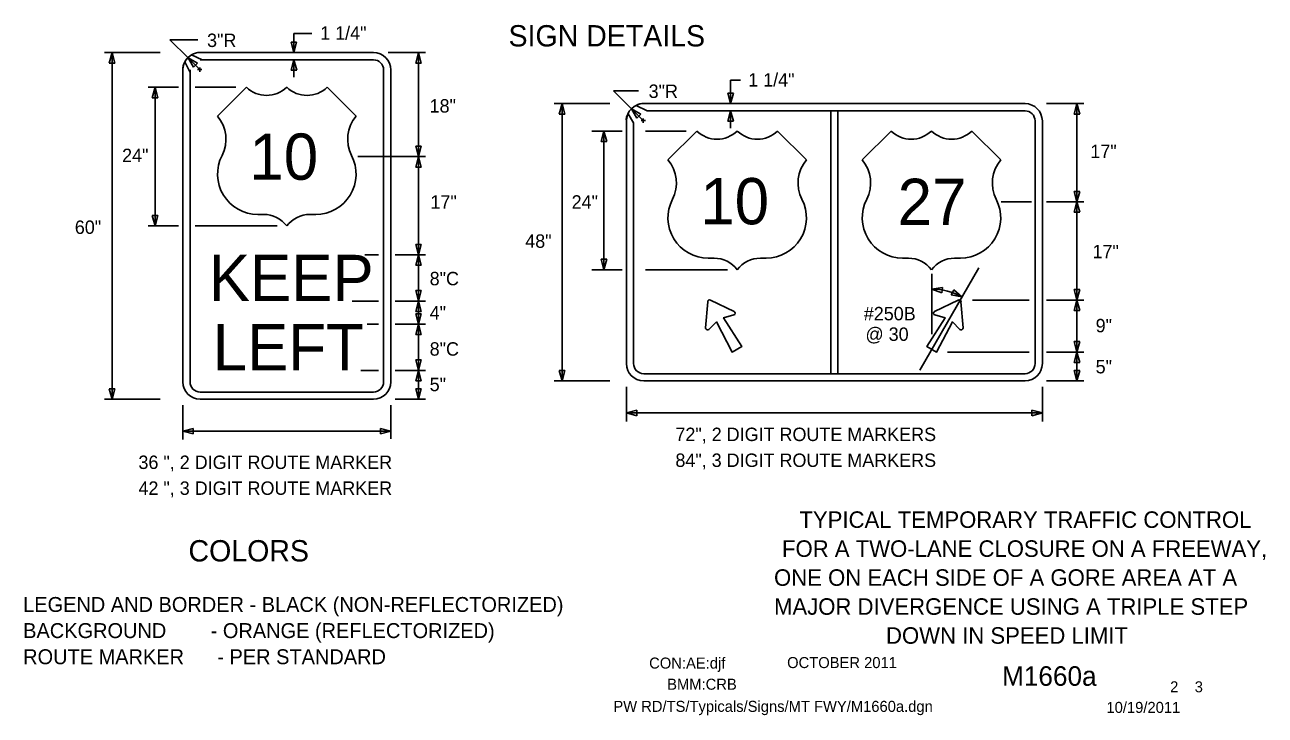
# Model space of a CAD drawing. Extents: x 16519 to 19508, y 5743 to 6974.
# Drawn here: x 17768 to 18466, y 5932 to 6320 of the extents above; entities that cross this region are included whole.
import ezdxf

# ---------------------------------------------------------------- set-up
doc = ezdxf.new("R2010")
doc.units = 0
for name, color, linetype in [('BORDER', 7, 'Continuous'), ('BORDER_SIGNAL_WO', 7, 'Continuous'), ('TRAFFIC_SIGNS_PR', 7, 'Continuous'), ('TYPICAL_EX', 7, 'Continuous'), ('TYPICAL_TEXT_DIMEN_PR', 7, 'Continuous')]:
    doc.layers.add(name, color=color, linetype=linetype)

msp = doc.modelspace()

# ---------------------------------------------------------------- linework, layer by layer
at = {"layer": 'TRAFFIC_SIGNS_PR'}
for p, q in [((17859.5, 6300.96), (17858.5, 6299.45)), ((17868.29, 6300.52), (17862.19, 6303.27)), ((17867.09, 6304.58), (17964.59, 6304.58)), ((17857.34, 6119.33), (17857.34, 6294.83)), ((17858.53, 6299.39), (17861.4, 6293.35)), ((17861.4, 6294.83), (17861.4, 6119.33)), ((17964.59, 6300.52), (17867.09, 6300.52)), ((17970.27, 6119.33), (17970.27, 6294.83)), ((17974.34, 6294.83), (17974.34, 6119.33)), ((18118.56, 6271.83), (18112.33, 6274.85)), ((18116.61, 6275.88), (18331.11, 6275.88)), ((18116.61, 6275.88), (18331.11, 6275.88)), ((18106.86, 6266.13), (18106.86, 6129.63)), ((18106.86, 6129.63), (18106.86, 6266.13)), ((18107.78, 6270.14), (18110.91, 6265.1)), ((18118.55, 6271.82), (18221.83, 6271.82)), ((18331.11, 6271.82), (18118.55, 6271.82)), ((18221.83, 6271.82), (18221.83, 6123.95)), ((18225.89, 6271.82), (18225.89, 6123.95)), ((18225.89, 6271.82), (18331.11, 6271.82)), ((18336.8, 6266.13), (18336.8, 6220.38)), ((18336.8, 6129.63), (18336.8, 6266.13)), ((18340.86, 6266.13), (18340.86, 6129.63)), ((18340.86, 6266.13), (18340.86, 6129.63)), ((18110.92, 6265.08), (18110.92, 6129.63)), ((18110.92, 6265.08), (18110.92, 6129.63)), ((18336.8, 6220.38), (18336.8, 6129.63)), ((18151.46, 6149.74), (18152.61, 6164.46)), ((18154.12, 6165.33), (18167.44, 6158.97)), ((18293.59, 6165.33), (18280.28, 6158.97)), ((18296.26, 6149.74), (18295.1, 6164.46)), ((18116.61, 6123.95), (18331.11, 6123.95)), ((18116.61, 6119.88), (18331.11, 6119.88)), ((18331.11, 6119.88), (18116.61, 6119.88)), ((17867.09, 6113.64), (17964.59, 6113.64)), ((17964.59, 6109.58), (17867.09, 6109.58))]:
    msp.add_line(p, q, dxfattribs=at)
for points in [[(18118.55, 6271.82), (18118.53, 6271.83)], [(18110.91, 6265.1), (18110.92, 6265.08)], [(18167.28, 6157), (18161.55, 6155.42), (18171.77, 6139.25), (18166.37, 6136.13), (18157.48, 6153.07), (18153.25, 6148.9)], [(18280.44, 6157), (18286.16, 6155.42), (18275.95, 6139.25), (18281.34, 6136.13), (18290.24, 6153.07), (18294.46, 6148.9)]]:
    msp.add_lwpolyline(points, dxfattribs=at)
msp.add_lwpolyline([(18221.83, 6271.82), (18225.89, 6271.82), (18225.89, 6123.95), (18221.83, 6123.95)], close=True, dxfattribs=at)
for centre, radius, start, end in [((17867.09, 6294.83), 9.75, 90, 180), ((17866.5, 6297.01), 7.6, 85.58319, 124.53531), ((17964.59, 6294.83), 9.75, 0, 90), ((17864.37, 6295.43), 7.06, 145.86811, 184.82317), ((17855.94, 6294.09), 5.51, 352.24294, 7.75653), ((17867.69, 6304.95), 4.47, 262.2432, 277.7568), ((17964.59, 6294.83), 5.69, 0, 90), ((18116.61, 6266.13), 9.75, 90, 180), ((18116.61, 6266.13), 9.75, 90, 180), ((18115.93, 6269.32), 6.6, 84.11162, 123.06374), ((18331.11, 6266.13), 9.75, 0, 90), ((18331.11, 6266.13), 9.75, 0, 90), ((18112.99, 6266.84), 6.17, 147.60925, 186.56283), ((18117.55, 6279), 7.24, 277.81035, 278.05403), ((18331.11, 6266.13), 5.69, 0, 89.99421), ((18331.11, 6266.13), 5.69, 0, 90), ((18153.67, 6164.37), 1.06, 64.48226, 175.51774), ((18294.05, 6164.37), 1.06, 4.48226, 115.51774), ((18166.98, 6158.02), 1.06, 285.9885, 64.48226), ((18280.73, 6158.02), 1.06, 115.51774, 254.0115), ((18152.52, 6149.66), 1.06, 175.51775, 314.01151), ((18295.2, 6149.66), 1.06, 225.98849, 4.48225), ((18116.61, 6129.63), 9.75, 180, 270), ((18116.61, 6129.63), 9.75, 180, 270), ((18116.61, 6129.63), 5.69, 180, 270), ((18116.61, 6129.63), 5.69, 180, 270), ((18331.11, 6129.63), 9.75, 270, 0), ((18331.11, 6129.63), 5.69, 270, 0), ((18331.11, 6129.63), 9.75, 270, 0), ((18331.11, 6129.63), 5.69, 270, 0), ((17867.09, 6119.33), 9.75, 180, 270), ((17867.09, 6119.33), 5.69, 180, 270), ((17964.59, 6119.33), 5.69, 270, 0), ((17964.59, 6119.33), 9.75, 270, 0)]:
    msp.add_arc(centre, radius, start, end, dxfattribs=at)
at = {"layer": 'TYPICAL_EX'}
for p, q in [((17876.84, 6268.84), (17893.09, 6285.09)), ((17954.84, 6268.84), (17938.59, 6285.09)), ((18130.22, 6244.22), (18146.47, 6260.47)), ((18208.22, 6244.22), (18191.97, 6260.47)), ((18239.5, 6244.22), (18255.75, 6260.47)), ((18317.5, 6244.22), (18301.25, 6260.47)), ((17899.56, 6213.54), (17902.81, 6213.54)), ((17932.11, 6213.54), (17928.86, 6213.54)), ((18152.95, 6188.93), (18156.2, 6188.93)), ((18185.49, 6188.93), (18182.24, 6188.93)), ((18262.22, 6188.93), (18265.47, 6188.93)), ((18294.77, 6188.93), (18291.52, 6188.93))]:
    msp.add_line(p, q, dxfattribs=at)
for centre, radius, start, end in [((17904.46, 6296.92), 16.42, 226.14041, 313.85958), ((17927.21, 6296.92), 16.42, 226.14042, 313.85959), ((17861.44, 6255.82), 20.16, 333.09768, 40.19361), ((17970.24, 6255.82), 20.16, 139.80639, 206.90233), ((18157.85, 6272.31), 16.42, 226.14041, 313.85958), ((18180.59, 6272.31), 16.42, 226.14042, 313.85959), ((18267.12, 6272.31), 16.42, 226.14041, 313.85958), ((18289.87, 6272.31), 16.42, 226.14042, 313.85959), ((17899.6, 6236.27), 22.73, 152.6698, 269.90132), ((17932.07, 6236.27), 22.73, 270.09868, 27.3302), ((18114.82, 6231.21), 20.16, 333.09768, 40.19361), ((18223.62, 6231.21), 20.16, 139.80639, 206.90233), ((18224.1, 6231.21), 20.16, 333.09768, 40.19361), ((18332.9, 6231.21), 20.16, 139.80639, 206.90233), ((18152.99, 6211.66), 22.73, 152.6698, 269.90132), ((18185.45, 6211.66), 22.73, 270.09868, 27.3302), ((18262.27, 6211.66), 22.73, 152.6698, 269.90132), ((18294.73, 6211.66), 22.73, 270.09868, 27.3302), ((17902.85, 6197.26), 16.28, 37.1038, 90.13853), ((17928.82, 6197.26), 16.28, 89.86147, 142.8962), ((18156.24, 6172.65), 16.28, 37.1038, 90.13853), ((18182.2, 6172.65), 16.28, 89.86147, 142.8962), ((18265.52, 6172.65), 16.28, 37.1038, 90.13853), ((18291.48, 6172.65), 16.28, 89.86147, 142.8962)]:
    msp.add_arc(centre, radius, start, end, dxfattribs=at)
at = {"layer": 'TYPICAL_TEXT_DIMEN_PR'}
for p, q in [((17919.81, 6315.34), (17919.81, 6304.58)), ((17919.81, 6315.34), (17929.91, 6315.34)), ((17865.71, 6311.86), (17850.05, 6311.86)), ((17850.05, 6311.86), (17860.29, 6301.63)), ((17919.81, 6304.58), (17918.24, 6310.44)), ((17918.24, 6310.44), (17919.81, 6310.44)), ((17919.81, 6310.44), (17921.38, 6310.44)), ((17921.38, 6310.44), (17919.81, 6304.58)), ((17844.51, 6304.58), (17813.21, 6304.58)), ((17815.98, 6298.72), (17817.55, 6304.58)), ((17817.55, 6304.58), (17817.55, 6109.58)), ((17817.55, 6304.58), (17819.12, 6298.72)), ((17860.29, 6301.63), (17866.85, 6295.07)), ((17863.32, 6296.37), (17860.29, 6301.63)), ((17860.29, 6301.63), (17865.54, 6298.6)), ((17972.88, 6304.58), (17993.84, 6304.58)), ((17988.37, 6298.72), (17989.94, 6304.58)), ((17989.94, 6304.58), (17989.94, 6246.08)), ((17989.94, 6304.58), (17991.51, 6298.72)), ((17817.55, 6298.72), (17815.98, 6298.72)), ((17819.12, 6298.72), (17817.55, 6298.72)), ((17864.43, 6297.49), (17863.32, 6296.37)), ((17865.54, 6298.6), (17864.43, 6297.49)), ((17865.64, 6295.07), (17868.05, 6295.07)), ((17866.85, 6293.86), (17866.85, 6296.28)), ((17918.28, 6294.66), (17919.86, 6300.52)), ((17919.86, 6294.66), (17918.28, 6294.66)), ((17919.86, 6300.52), (17919.86, 6290.77)), ((17919.86, 6300.52), (17921.43, 6294.66)), ((17921.43, 6294.66), (17919.86, 6294.66)), ((17989.94, 6298.72), (17988.37, 6298.72)), ((17991.51, 6298.72), (17989.94, 6298.72)), ((18165.47, 6289.03), (18165.47, 6275.88)), ((18165.47, 6289.03), (18170.99, 6289.03)), ((17854.96, 6285.08), (17837.84, 6285.08)), ((17840.16, 6279.22), (17841.73, 6285.08)), ((17841.73, 6285.08), (17841.73, 6207.08)), ((17841.73, 6285.08), (17843.3, 6279.22)), ((17887.2, 6285.08), (17864.33, 6285.08)), ((18113.75, 6283.17), (18099.57, 6283.17)), ((18099.57, 6283.17), (18109.72, 6273.02)), ((18165.47, 6275.88), (18163.89, 6281.74)), ((18163.89, 6281.74), (18165.47, 6281.74)), ((18165.47, 6281.74), (18167.04, 6281.74)), ((18167.04, 6281.74), (18165.47, 6275.88)), ((17841.73, 6279.22), (17840.16, 6279.22)), ((17843.3, 6279.22), (17841.73, 6279.22)), ((18097.62, 6275.88), (18066.33, 6275.88)), ((18069.1, 6270.02), (18070.67, 6275.88)), ((18070.67, 6275.88), (18070.67, 6119.88)), ((18070.67, 6275.88), (18072.24, 6270.02)), ((18109.72, 6273.02), (18116.37, 6266.37)), ((18112.76, 6267.76), (18109.72, 6273.02)), ((18109.72, 6273.02), (18114.98, 6269.99)), ((18343.23, 6275.88), (18364.19, 6275.88)), ((18358.72, 6270.02), (18360.29, 6275.88)), ((18360.29, 6275.88), (18360.29, 6220.63)), ((18360.29, 6275.88), (18361.86, 6270.02)), ((18070.67, 6270.02), (18069.1, 6270.02)), ((18072.24, 6270.02), (18070.67, 6270.02)), ((18113.87, 6268.88), (18112.76, 6267.76)), ((18114.98, 6269.99), (18113.87, 6268.88)), ((18115.16, 6266.37), (18117.58, 6266.37)), ((18116.37, 6265.16), (18116.37, 6267.58)), ((18163.94, 6265.96), (18165.51, 6271.82)), ((18163.94, 6265.96), (18165.51, 6271.82)), ((18165.51, 6271.82), (18165.51, 6262.07)), ((18165.51, 6271.82), (18167.08, 6265.96)), ((18165.51, 6271.82), (18167.08, 6265.96)), ((18360.29, 6270.02), (18358.72, 6270.02)), ((18361.86, 6270.02), (18360.29, 6270.02)), ((18104.49, 6260.47), (18087.36, 6260.47)), ((18092.65, 6254.61), (18094.23, 6260.47)), ((18094.23, 6260.47), (18094.23, 6182.47)), ((18094.23, 6260.47), (18095.8, 6254.61)), ((18140.59, 6260.47), (18117.71, 6260.47)), ((18165.51, 6265.96), (18163.94, 6265.96)), ((18165.51, 6265.96), (18163.94, 6265.96)), ((18167.08, 6265.96), (18165.51, 6265.96)), ((18167.08, 6265.96), (18165.51, 6265.96)), ((18094.23, 6254.61), (18092.65, 6254.61)), ((18095.8, 6254.61), (18094.23, 6254.61)), ((17955.73, 6246.08), (17993.84, 6246.08)), ((17989.94, 6246.08), (17988.37, 6251.94)), ((17988.37, 6251.94), (17989.94, 6251.94)), ((17988.37, 6240.22), (17989.94, 6246.08)), ((17989.94, 6251.94), (17991.51, 6251.94)), ((17991.51, 6251.94), (17989.94, 6246.08)), ((17989.94, 6246.08), (17989.94, 6190.83)), ((17989.94, 6246.08), (17991.51, 6240.22)), ((17989.94, 6240.22), (17988.37, 6240.22)), ((17991.51, 6240.22), (17989.94, 6240.22)), ((18360.29, 6220.63), (18358.72, 6226.49)), ((18358.72, 6226.49), (18360.29, 6226.49)), ((18360.29, 6226.49), (18361.86, 6226.49)), ((18361.86, 6226.49), (18360.29, 6220.63)), ((18317.67, 6220.63), (18334.82, 6220.63)), ((18343.23, 6220.63), (18364.19, 6220.63)), ((18358.72, 6214.77), (18360.29, 6220.63)), ((18360.29, 6220.63), (18360.29, 6165.38)), ((18360.29, 6220.63), (18361.86, 6214.77)), ((17841.73, 6207.08), (17840.16, 6212.94)), ((17840.16, 6212.94), (17841.73, 6212.94)), ((17841.73, 6212.94), (17843.3, 6212.94)), ((17843.3, 6212.94), (17841.73, 6207.08)), ((18360.29, 6214.77), (18358.72, 6214.77)), ((18361.86, 6214.77), (18360.29, 6214.77)), ((17854.96, 6207.08), (17837.84, 6207.08)), ((17910.33, 6207.08), (17864.33, 6207.08)), ((17989.94, 6190.83), (17988.37, 6196.69)), ((17988.37, 6196.69), (17989.94, 6196.69)), ((17989.94, 6196.69), (17991.51, 6196.69)), ((17991.51, 6196.69), (17989.94, 6190.83)), ((17959.66, 6190.83), (17967.35, 6190.83)), ((17976.71, 6190.83), (17993.84, 6190.83)), ((17988.37, 6184.97), (17989.94, 6190.83)), ((17989.94, 6190.83), (17989.94, 6164.83)), ((17989.94, 6190.83), (17991.51, 6184.97)), ((17989.94, 6184.97), (17988.37, 6184.97)), ((17991.51, 6184.97), (17989.94, 6184.97)), ((18104.49, 6182.47), (18087.36, 6182.47)), ((18094.23, 6182.47), (18092.65, 6188.33)), ((18092.65, 6188.33), (18094.23, 6188.33)), ((18094.23, 6188.33), (18095.8, 6188.33)), ((18095.8, 6188.33), (18094.23, 6182.47)), ((18163.71, 6182.47), (18117.71, 6182.47)), ((18271.89, 6125.98), (18305.13, 6183.57)), ((18278.65, 6146.14), (18278.65, 6180.13)), ((17989.94, 6164.83), (17988.37, 6170.69)), ((17988.37, 6170.69), (17989.94, 6170.69)), ((17989.94, 6170.69), (17991.51, 6170.69)), ((17991.51, 6170.69), (17989.94, 6164.83)), ((18278.67, 6171.58), (18284.67, 6172.54)), ((18284.35, 6169.41), (18278.67, 6171.58)), ((18284.51, 6170.97), (18284.35, 6169.41)), ((18284.67, 6172.54), (18284.51, 6170.97)), ((18289.66, 6168.25), (18290.34, 6169.67)), ((18290.34, 6169.67), (18291.03, 6171.08)), ((18291.03, 6171.08), (18295.62, 6167.12)), ((18360.29, 6165.38), (18358.72, 6171.24)), ((18358.72, 6171.24), (18360.29, 6171.24)), ((18360.29, 6171.24), (18361.86, 6171.24)), ((18361.86, 6171.24), (18360.29, 6165.38)), ((17952.65, 6164.83), (17967.35, 6164.83)), ((17976.71, 6164.83), (17993.84, 6164.83)), ((17988.37, 6158.97), (17989.94, 6164.83)), ((17989.94, 6164.83), (17989.94, 6151.83)), ((17989.94, 6164.83), (17991.51, 6158.97)), ((18295.62, 6167.12), (18289.66, 6168.25)), ((18301.6, 6165.38), (18333.47, 6165.38)), ((18343.23, 6165.38), (18364.19, 6165.38)), ((18358.72, 6159.52), (18360.29, 6165.38)), ((18360.29, 6165.38), (18360.29, 6136.13)), ((18360.29, 6165.38), (18361.86, 6159.52)), ((17989.94, 6158.97), (17988.37, 6158.97)), ((17989.94, 6151.83), (17988.37, 6157.69)), ((17988.37, 6157.69), (17989.94, 6157.69)), ((17991.51, 6158.97), (17989.94, 6158.97)), ((17989.94, 6157.69), (17991.51, 6157.69)), ((17991.51, 6157.69), (17989.94, 6151.83)), ((18360.29, 6159.52), (18358.72, 6159.52)), ((18361.86, 6159.52), (18360.29, 6159.52)), ((17961, 6151.83), (17967.35, 6151.83)), ((17976.71, 6151.83), (17993.84, 6151.83)), ((17988.37, 6145.97), (17989.94, 6151.83)), ((17989.94, 6151.83), (17989.94, 6125.83)), ((17989.94, 6151.83), (17991.51, 6145.97)), ((17989.94, 6145.97), (17988.37, 6145.97)), ((17991.51, 6145.97), (17989.94, 6145.97)), ((18360.29, 6136.13), (18358.72, 6141.99)), ((18358.72, 6141.99), (18360.29, 6141.99)), ((18360.29, 6141.99), (18361.86, 6141.99)), ((18361.86, 6141.99), (18360.29, 6136.13)), ((18287.46, 6136.13), (18333.47, 6136.13)), ((18343.23, 6136.13), (18364.19, 6136.13)), ((18358.72, 6130.27), (18360.29, 6136.13)), ((18360.29, 6136.13), (18360.29, 6119.88)), ((18360.29, 6136.13), (18361.86, 6130.27)), ((17989.94, 6125.83), (17988.37, 6131.69)), ((17988.37, 6131.69), (17989.94, 6131.69)), ((17989.94, 6131.69), (17991.51, 6131.69)), ((17991.51, 6131.69), (17989.94, 6125.83)), ((18360.29, 6130.27), (18358.72, 6130.27)), ((18361.86, 6130.27), (18360.29, 6130.27)), ((17957.5, 6125.83), (17967.35, 6125.83)), ((17976.71, 6125.83), (17993.84, 6125.83)), ((17988.37, 6119.97), (17989.94, 6125.83)), ((17989.94, 6119.97), (17988.37, 6119.97)), ((17989.94, 6125.83), (17989.94, 6109.58)), ((17989.94, 6125.83), (17991.51, 6119.97)), ((17991.51, 6119.97), (17989.94, 6119.97)), ((18097.62, 6119.88), (18066.33, 6119.88)), ((18070.67, 6119.88), (18069.1, 6125.74)), ((18069.1, 6125.74), (18070.67, 6125.74)), ((18070.67, 6125.74), (18072.24, 6125.74)), ((18072.24, 6125.74), (18070.67, 6119.88)), ((18343.23, 6119.88), (18360.36, 6119.88)), ((18343.23, 6119.88), (18364.19, 6119.88)), ((18343.23, 6119.88), (18360.36, 6119.88)), ((18360.29, 6119.88), (18358.72, 6125.74)), ((18358.72, 6125.74), (18360.29, 6125.74)), ((18360.29, 6125.74), (18361.86, 6125.74)), ((18361.86, 6125.74), (18360.29, 6119.88)), ((17817.55, 6109.58), (17815.98, 6115.44)), ((17815.98, 6115.44), (17817.55, 6115.44)), ((17817.55, 6115.44), (17819.12, 6115.44)), ((17819.12, 6115.44), (17817.55, 6109.58)), ((17989.94, 6109.58), (17988.37, 6115.44)), ((17988.37, 6115.44), (17989.94, 6115.44)), ((17989.94, 6115.44), (17991.51, 6115.44)), ((17991.51, 6115.44), (17989.94, 6109.58)), ((18106.86, 6116.54), (18106.86, 6096.98)), ((18340.86, 6116.54), (18340.86, 6096.98)), ((17844.51, 6109.58), (17813.21, 6109.58)), ((17857.34, 6106.24), (17857.34, 6086.89)), ((17974.34, 6106.24), (17974.34, 6087.34)), ((17976.71, 6109.58), (17993.84, 6109.58)), ((18106.86, 6101.91), (18112.72, 6103.48)), ((18106.86, 6101.91), (18340.86, 6101.91)), ((18112.72, 6100.34), (18106.86, 6101.91)), ((18112.72, 6103.48), (18112.72, 6101.91)), ((18112.72, 6101.91), (18112.72, 6100.34)), ((18335, 6101.91), (18335, 6103.48)), ((18335, 6103.48), (18340.86, 6101.91)), ((18340.86, 6101.91), (18335, 6100.34)), ((18335, 6100.34), (18335, 6101.91)), ((17857.34, 6091.61), (17863.2, 6093.18)), ((17857.34, 6091.61), (17974.34, 6091.61)), ((17863.2, 6090.04), (17857.34, 6091.61)), ((17863.2, 6093.18), (17863.2, 6091.61)), ((17863.2, 6091.61), (17863.2, 6090.04)), ((17968.47, 6091.61), (17968.47, 6093.18)), ((17968.47, 6093.18), (17974.34, 6091.61)), ((17974.34, 6091.61), (17968.47, 6090.04)), ((17968.47, 6090.04), (17968.47, 6091.61))]:
    msp.add_line(p, q, dxfattribs=at)
msp.add_arc((18278.84, 6137.14), 34.39, 60.74521, 90.32117, dxfattribs=at)

# ---------------------------------------------------------------- texts
at = {"layer": 'BORDER'}
for s, p in [('TYPICAL TEMPORARY TRAFFIC CONTROL', (18204.21, 6037.21)), ('FOR A TWO-LANE CLOSURE ON A FREEWAY,', (18194.41, 6020.91)), ('ONE ON EACH SIDE OF A GORE AREA AT A ', (18189.92, 6004.62)), ('MAJOR DIVERGENCE USING A TRIPLE STEP ', (18189.92, 5988.32)), ('DOWN IN SPEED LIMIT', (18252.92, 5972.02))]:
    msp.add_text(s, height=9.3, dxfattribs=at).set_placement(p)
at = {"layer": 'BORDER_SIGNAL_WO'}
for s, height, p in [('CON:AE:djf  ', 6.2, (18119.69, 5958.06)), ('    OCTOBER 2011    ', 6.2, (18188.08, 5958.34)), ('    M1660a   ', 11, (18301.86, 5948.38)), ('BMM:CRB   ', 6.2, (18129.81, 5946.17)), (' 2    3 ', 6.2, (18410.45, 5944.7)), ('PW RD/TS/Typicals/Signs/MT FWY/M1660a.dgn      ', 6.2, (18099.55, 5933.71)), ('10/19/2011    ', 6.2, (18376.93, 5933.13))]:
    msp.add_text(s, height=height, dxfattribs=at).set_placement(p)
at = {"layer": 'TRAFFIC_SIGNS_PR'}
for s, p in [('10', (17894.81, 6233.08)), ('10', (18148.46, 6208.01)), ('27', (18259.47, 6207.65)), ('KEEP', (17871.94, 6164.83)), ('LEFT', (17874.17, 6125.83))]:
    msp.add_text(s, height=26, dxfattribs=at).set_placement(p)
at = {"layer": 'TYPICAL_TEXT_DIMEN_PR'}
for s, height, p in [('3"R', 7.55, (17870.98, 6307.74)), ('1 1/4"', 7.55, (17934.61, 6311.84)), ('SIGN DETAILS', 12, (18040.56, 6308.05)), ('1 1/4"', 7.55, (18175.39, 6285.46)), ('3"R', 7.55, (18119.39, 6279.09)), ('18"', 7.55, (17996.18, 6270.85)), ('17"', 7.55, (18367.87, 6245.24)), ('24"', 7.55, (17823.18, 6242.97)), ('17"', 7.55, (17996.64, 6216.81)), ('24"', 7.55, (18076.08, 6216.8)), ('60"', 7.55, (17796.58, 6202.6)), ('48"', 7.55, (18049.97, 6194.78)), ('17"', 7.55, (18369.07, 6188.89)), ('8"C', 7.55, (17996.21, 6173.69)), ('4" ', 7.55, (17996.21, 6154.43)), ('#250B', 7.55, (18240.42, 6153.98)), ('9"', 7.55, (18370.85, 6147.23)), ('@ 30', 7.55, (18241.36, 6142.43)), ('8"C', 7.55, (17996.21, 6134.1)), ('5"', 7.55, (18370.85, 6124.13)), ('5" ', 7.55, (17996.21, 6114.13)), ('72", 2 DIGIT ROUTE MARKERS', 7.55, (18134.44, 6086.05)), ('36 ", 2 DIGIT ROUTE MARKER', 7.55, (17832.38, 6070.35)), ('84", 3 DIGIT ROUTE MARKERS', 7.55, (18134.44, 6071.5)), ('42 ", 3 DIGIT ROUTE MARKER', 7.55, (17832.38, 6055.8)), ('COLORS', 12, (17860.53, 6018.33)), ('LEGEND AND BORDER - BLACK (NON-REFLECTORIZED)', 8.4, (17767.53, 5989.92)), ('BACKGROUND        - ORANGE (REFLECTORIZED)', 8.4, (17767.53, 5975.22)), ('ROUTE MARKER      - PER STANDARD', 8.4, (17767.53, 5960.52))]:
    msp.add_text(s, height=height, dxfattribs=at).set_placement(p)

doc.saveas('drawing.dxf')
